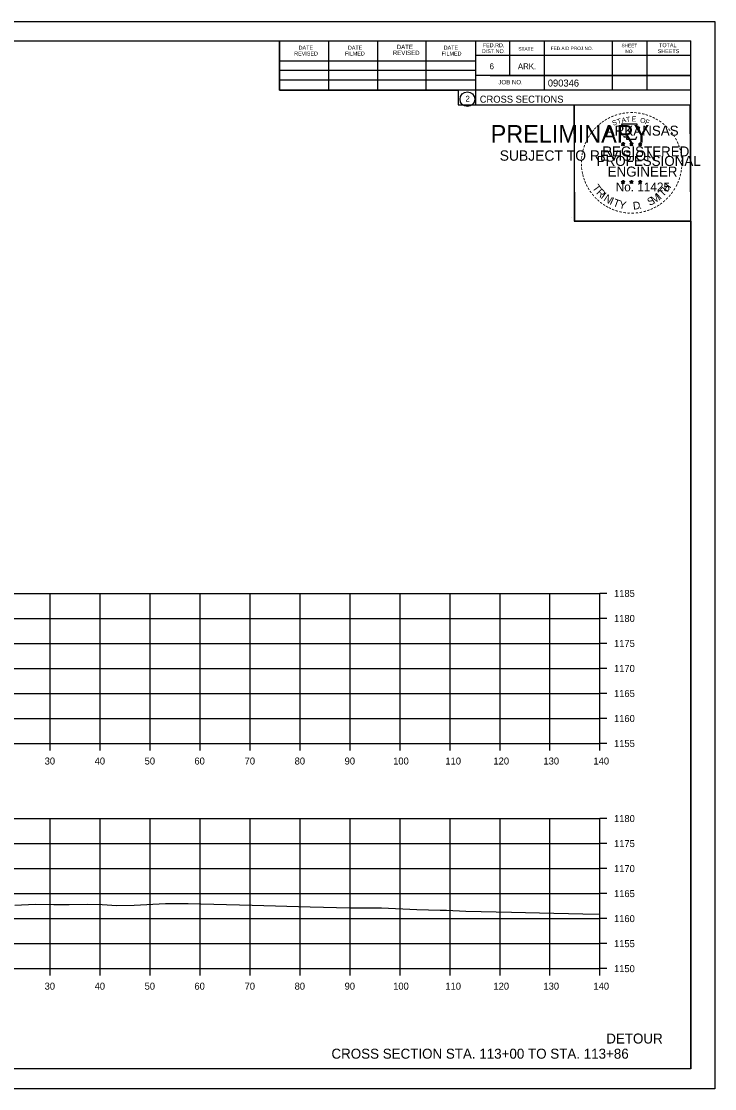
# Model space of a CAD drawing. Extents: x 1368971 to 1374497, y 378717 to 381839.
# Drawn here: x 1371286.9 to 1371425.6, y 381626.1 to 381839.4 of the extents above; entities that cross this region are included whole.
import ezdxf

# ---------------------------------------------------------------- set-up
doc = ezdxf.new("R2010")
doc.units = 0
for name, color, linetype in [('R_Axis', 7, 'Continuous'), ('R_Axis Annot', 7, 'Continuous'), ('R_Draft', 7, 'Continuous'), ('R_Exist Surface', 7, 'Continuous'), ('R_Grid', 7, 'Continuous'), ('R_No Plot', 7, 'Continuous')]:
    doc.layers.add(name, color=color, linetype=linetype)

msp = doc.modelspace()

# ---------------------------------------------------------------- linework, layer by layer
at = {"layer": 'R_Axis'}
for p, q in [((1371402.64, 381695.09), (1371402.64, 381725.09)), ((1371404.04, 381725.09), (1371402.64, 381725.09)), ((1371404.04, 381720.09), (1371402.64, 381720.09)), ((1371404.04, 381715.09), (1371402.64, 381715.09)), ((1371404.04, 381710.09), (1371402.64, 381710.09)), ((1371404.04, 381705.09), (1371402.64, 381705.09)), ((1371404.04, 381700.09), (1371402.64, 381700.09)), ((1371122.64, 381695.09), (1371402.64, 381695.09)), ((1371292.64, 381693.69), (1371292.64, 381695.09)), ((1371302.64, 381693.69), (1371302.64, 381695.09)), ((1371312.64, 381693.69), (1371312.64, 381695.09)), ((1371322.64, 381693.69), (1371322.64, 381695.09)), ((1371332.64, 381693.69), (1371332.64, 381695.09)), ((1371342.64, 381693.69), (1371342.64, 381695.09)), ((1371352.64, 381693.69), (1371352.64, 381695.09)), ((1371362.64, 381693.69), (1371362.64, 381695.09)), ((1371372.64, 381693.69), (1371372.64, 381695.09)), ((1371382.64, 381693.69), (1371382.64, 381695.09)), ((1371392.64, 381693.69), (1371392.64, 381695.09)), ((1371402.64, 381693.69), (1371402.64, 381695.09)), ((1371404.04, 381695.09), (1371402.64, 381695.09)), ((1371402.64, 381650.09), (1371402.64, 381680.09)), ((1371404.04, 381680.09), (1371402.64, 381680.09)), ((1371404.04, 381675.09), (1371402.64, 381675.09)), ((1371404.04, 381670.09), (1371402.64, 381670.09)), ((1371404.04, 381665.09), (1371402.64, 381665.09)), ((1371404.04, 381660.09), (1371402.64, 381660.09)), ((1371404.04, 381655.09), (1371402.64, 381655.09)), ((1371122.64, 381650.09), (1371402.64, 381650.09)), ((1371292.64, 381648.69), (1371292.64, 381650.09)), ((1371302.64, 381648.69), (1371302.64, 381650.09)), ((1371312.64, 381648.69), (1371312.64, 381650.09)), ((1371322.64, 381648.69), (1371322.64, 381650.09)), ((1371332.64, 381648.69), (1371332.64, 381650.09)), ((1371342.64, 381648.69), (1371342.64, 381650.09)), ((1371352.64, 381648.69), (1371352.64, 381650.09)), ((1371362.64, 381648.69), (1371362.64, 381650.09)), ((1371372.64, 381648.69), (1371372.64, 381650.09)), ((1371382.64, 381648.69), (1371382.64, 381650.09)), ((1371392.64, 381648.69), (1371392.64, 381650.09)), ((1371402.64, 381648.69), (1371402.64, 381650.09)), ((1371404.04, 381650.09), (1371402.64, 381650.09))]:
    msp.add_line(p, q, dxfattribs=at)
at = {"layer": 'R_Exist Surface'}
msp.add_lwpolyline([(1371285.58, 381662.81), (1371289.64, 381662.95), (1371293.37, 381662.89), (1371296.47, 381662.94), (1371300.23, 381662.98), (1371303.08, 381662.94), (1371306, 381662.7), (1371309.44, 381662.8), (1371315.75, 381663.08), (1371320.25, 381663.08), (1371333.1, 381662.77), (1371344.7, 381662.45), (1371352.61, 381662.24), (1371358.96, 381662.25), (1371365.99, 381661.93), (1371370.64, 381661.8), (1371371.96, 381661.81), (1371375.79, 381661.61), (1371384.93, 381661.38), (1371390.56, 381661.28), (1371399.24, 381661.07), (1371402.64, 381660.99)], dxfattribs=at)
at = {"layer": 'R_Grid'}
for p, q in [((1371122.64, 381725.09), (1371402.64, 381725.09)), ((1371292.64, 381695.09), (1371292.64, 381725.09)), ((1371302.64, 381695.09), (1371302.64, 381725.09)), ((1371312.64, 381695.09), (1371312.64, 381725.09)), ((1371322.64, 381695.09), (1371322.64, 381725.09)), ((1371332.64, 381695.09), (1371332.64, 381725.09)), ((1371342.64, 381695.09), (1371342.64, 381725.09)), ((1371352.64, 381695.09), (1371352.64, 381725.09)), ((1371362.64, 381695.09), (1371362.64, 381725.09)), ((1371372.64, 381695.09), (1371372.64, 381725.09)), ((1371382.64, 381695.09), (1371382.64, 381725.09)), ((1371392.64, 381695.09), (1371392.64, 381725.09)), ((1371402.64, 381695.09), (1371402.64, 381725.09)), ((1371122.64, 381720.09), (1371402.64, 381720.09)), ((1371122.64, 381715.09), (1371402.64, 381715.09)), ((1371122.64, 381710.09), (1371402.64, 381710.09)), ((1371122.64, 381705.09), (1371402.64, 381705.09)), ((1371122.64, 381700.09), (1371402.64, 381700.09)), ((1371122.64, 381695.09), (1371402.64, 381695.09)), ((1371122.64, 381680.09), (1371402.64, 381680.09)), ((1371292.64, 381650.09), (1371292.64, 381680.09)), ((1371302.64, 381650.09), (1371302.64, 381680.09)), ((1371312.64, 381650.09), (1371312.64, 381680.09)), ((1371322.64, 381650.09), (1371322.64, 381680.09)), ((1371332.64, 381650.09), (1371332.64, 381680.09)), ((1371342.64, 381650.09), (1371342.64, 381680.09)), ((1371352.64, 381650.09), (1371352.64, 381680.09)), ((1371362.64, 381650.09), (1371362.64, 381680.09)), ((1371372.64, 381650.09), (1371372.64, 381680.09)), ((1371382.64, 381650.09), (1371382.64, 381680.09)), ((1371392.64, 381650.09), (1371392.64, 381680.09)), ((1371402.64, 381650.09), (1371402.64, 381680.09)), ((1371122.64, 381675.09), (1371402.64, 381675.09)), ((1371122.64, 381670.09), (1371402.64, 381670.09)), ((1371122.64, 381665.09), (1371402.64, 381665.09)), ((1371122.64, 381660.09), (1371402.64, 381660.09)), ((1371122.64, 381655.09), (1371402.64, 381655.09)), ((1371122.64, 381650.09), (1371402.64, 381650.09))]:
    msp.add_line(p, q, dxfattribs=at)
at = {"layer": 'R_No Plot'}
for p, q in [((1371092.24, 381839.44), (1371425.58, 381839.44)), ((1371104.64, 381835.55), (1371420.82, 381835.55)), ((1371338.56, 381825.67), (1371338.56, 381835.55)), ((1371348.42, 381825.67), (1371348.42, 381835.35)), ((1371358.18, 381825.67), (1371358.18, 381835.35)), ((1371367.86, 381825.67), (1371367.86, 381835.35)), ((1371377.72, 381835.55), (1371377.72, 381822.75)), ((1371384.56, 381835.55), (1371384.56, 381828.61)), ((1371391.5, 381835.55), (1371391.5, 381825.67)), ((1371405.08, 381835.55), (1371405.08, 381825.67)), ((1371412.02, 381835.55), (1371412.02, 381825.67)), ((1371420.82, 381630.09), (1371420.82, 381835.55)), ((1371420.82, 381832.61), (1371377.72, 381832.61)), ((1371420.82, 381832.63), (1371420.82, 381832.63)), ((1371338.56, 381831.53), (1371377.72, 381831.53)), ((1371338.56, 381829.67), (1371377.72, 381829.67)), ((1371338.56, 381825.67), (1371338.56, 381827.73)), ((1371338.56, 381827.73), (1371377.72, 381827.73)), ((1371420.82, 381828.61), (1371377.72, 381828.61)), ((1371380.68, 381828.61), (1371420.82, 381828.61)), ((1371420.82, 381825.67), (1371338.56, 381825.67)), ((1371377.72, 381822.75), (1371420.82, 381822.75)), ((1371406.91, 381815), (1371407.26, 381814.89)), ((1371406.91, 381815), (1371407.16, 381814.96)), ((1371406.91, 381815), (1371407.15, 381814.88)), ((1371407.04, 381814.59), (1371407.26, 381814.89)), ((1371407.04, 381814.59), (1371407.17, 381814.84)), ((1371407.04, 381814.59), (1371407.26, 381814.81)), ((1371407.26, 381815.26), (1371407.22, 381815)), ((1371407.26, 381814.89), (1371407.26, 381815.26)), ((1371407.26, 381815.26), (1371407.31, 381815.01)), ((1371407.6, 381815), (1371407.26, 381814.89)), ((1371407.47, 381814.59), (1371407.26, 381814.89)), ((1371407.47, 381814.59), (1371407.26, 381814.81)), ((1371407.6, 381815), (1371407.32, 381814.95)), ((1371407.47, 381814.59), (1371407.33, 381814.89)), ((1371407.6, 381815), (1371407.4, 381814.9)), ((1371408.58, 381815), (1371408.93, 381814.89)), ((1371408.58, 381815), (1371408.83, 381814.96)), ((1371408.58, 381815), (1371408.82, 381814.88)), ((1371408.71, 381814.59), (1371408.93, 381814.89)), ((1371408.71, 381814.59), (1371408.84, 381814.84)), ((1371408.71, 381814.59), (1371408.93, 381814.81)), ((1371408.93, 381815.26), (1371408.89, 381815)), ((1371408.93, 381814.89), (1371408.93, 381815.26)), ((1371408.93, 381815.26), (1371408.98, 381815.01)), ((1371409.27, 381815), (1371408.93, 381814.89)), ((1371409.14, 381814.59), (1371408.93, 381814.89)), ((1371409.14, 381814.59), (1371408.93, 381814.81)), ((1371409.27, 381815), (1371408.99, 381814.95)), ((1371409.14, 381814.59), (1371409, 381814.89)), ((1371409.27, 381815), (1371409.07, 381814.9)), ((1371410.34, 381814.99), (1371410.69, 381814.88)), ((1371410.34, 381814.99), (1371410.6, 381814.95)), ((1371410.34, 381814.99), (1371410.58, 381814.87)), ((1371410.48, 381814.58), (1371410.69, 381814.88)), ((1371410.48, 381814.58), (1371410.6, 381814.83)), ((1371410.48, 381814.58), (1371410.69, 381814.8)), ((1371410.69, 381815.24), (1371410.65, 381814.99)), ((1371410.69, 381814.88), (1371410.69, 381815.24)), ((1371410.69, 381815.24), (1371410.74, 381814.99)), ((1371411.04, 381814.99), (1371410.69, 381814.88)), ((1371410.9, 381814.58), (1371410.69, 381814.88)), ((1371410.9, 381814.58), (1371410.69, 381814.8)), ((1371411.04, 381814.99), (1371410.75, 381814.94)), ((1371410.9, 381814.58), (1371410.77, 381814.87)), ((1371411.04, 381814.99), (1371410.83, 381814.89)), ((1371406.9, 381807.43), (1371407.25, 381807.32)), ((1371406.9, 381807.43), (1371407.16, 381807.38)), ((1371406.9, 381807.43), (1371407.14, 381807.31)), ((1371407.04, 381807.02), (1371407.25, 381807.32)), ((1371407.04, 381807.02), (1371407.16, 381807.27)), ((1371407.04, 381807.02), (1371407.25, 381807.24)), ((1371407.25, 381807.68), (1371407.21, 381807.43)), ((1371407.25, 381807.32), (1371407.25, 381807.68)), ((1371407.25, 381807.68), (1371407.3, 381807.43)), ((1371407.6, 381807.43), (1371407.25, 381807.32)), ((1371407.47, 381807.02), (1371407.25, 381807.32)), ((1371407.47, 381807.02), (1371407.25, 381807.24)), ((1371407.6, 381807.43), (1371407.31, 381807.38)), ((1371407.47, 381807.02), (1371407.33, 381807.31)), ((1371407.6, 381807.43), (1371407.4, 381807.33)), ((1371408.57, 381807.43), (1371408.92, 381807.32)), ((1371408.57, 381807.43), (1371408.83, 381807.38)), ((1371408.57, 381807.43), (1371408.81, 381807.31)), ((1371408.71, 381807.02), (1371408.92, 381807.32)), ((1371408.71, 381807.02), (1371408.83, 381807.27)), ((1371408.71, 381807.02), (1371408.92, 381807.24)), ((1371408.92, 381807.68), (1371408.88, 381807.43)), ((1371408.92, 381807.32), (1371408.92, 381807.68)), ((1371408.92, 381807.68), (1371408.97, 381807.43)), ((1371409.27, 381807.43), (1371408.92, 381807.32)), ((1371409.14, 381807.02), (1371408.92, 381807.32)), ((1371409.14, 381807.02), (1371408.92, 381807.24)), ((1371409.27, 381807.43), (1371408.98, 381807.38)), ((1371409.14, 381807.02), (1371409, 381807.31)), ((1371409.27, 381807.43), (1371409.07, 381807.33)), ((1371410.34, 381807.42), (1371410.69, 381807.31)), ((1371410.34, 381807.42), (1371410.59, 381807.37)), ((1371410.34, 381807.42), (1371410.58, 381807.3)), ((1371410.47, 381807.01), (1371410.69, 381807.31)), ((1371410.47, 381807.01), (1371410.6, 381807.26)), ((1371410.47, 381807.01), (1371410.69, 381807.23)), ((1371410.69, 381807.67), (1371410.65, 381807.42)), ((1371410.69, 381807.31), (1371410.69, 381807.67)), ((1371410.69, 381807.67), (1371410.74, 381807.42)), ((1371411.04, 381807.42), (1371410.69, 381807.31)), ((1371410.9, 381807.01), (1371410.69, 381807.31)), ((1371410.9, 381807.01), (1371410.69, 381807.23)), ((1371411.04, 381807.42), (1371410.75, 381807.37)), ((1371410.9, 381807.01), (1371410.77, 381807.3)), ((1371411.04, 381807.42), (1371410.83, 381807.32)), ((1371396.86, 381800.29), (1371396.86, 381800.29)), ((1371420.82, 381630.09), (1371104.64, 381630.09)), ((1371092.24, 381626.11), (1371425.58, 381626.11))]:
    msp.add_line(p, q, dxfattribs=at)
for points in [[(1371092.24, 381839.44), (1371425.58, 381839.44), (1371425.58, 381626.1), (1371092.24, 381626.1)], [(1371338.56, 381835.55), (1371338.56, 381825.67), (1371374.3, 381825.67), (1371374.3, 381822.75), (1371397.49, 381822.75), (1371397.49, 381799.53), (1371420.82, 381799.53), (1371420.82, 381630.09), (1371104.64, 381630.09), (1371104.64, 381835.55)], [(1371397.49, 381822.78), (1371420.59, 381822.78), (1371420.71, 381799.53), (1371397.61, 381799.53)]]:
    msp.add_lwpolyline(points, close=True, dxfattribs=at)
for points in [[(1371406.95, 381818.88), (1371407.22, 381818.05)], [(1371410.46, 381817.96), (1371410.6, 381818.24), (1371409.92, 381818.22), (1371410.07, 381818.88), (1371406.95, 381818.88)], [(1371407.26, 381815.26), (1371407.47, 381814.59), (1371406.91, 381815), (1371407.6, 381815), (1371407.04, 381814.59), (1371407.26, 381815.26)], [(1371407.44, 381816.46), (1371407.44, 381816.37), (1371408, 381816.35), (1371407.95, 381815.88), (1371409.82, 381815.88), (1371410.02, 381816.41)], [(1371408.93, 381815.26), (1371409.14, 381814.59), (1371408.58, 381815), (1371409.27, 381815), (1371408.71, 381814.59), (1371408.93, 381815.26)], [(1371410.69, 381815.24), (1371410.9, 381814.58), (1371410.34, 381814.99), (1371411.04, 381814.99), (1371410.48, 381814.58), (1371410.69, 381815.24)], [(1371407.25, 381807.68), (1371407.47, 381807.02), (1371406.9, 381807.43), (1371407.6, 381807.43), (1371407.04, 381807.02), (1371407.25, 381807.68)], [(1371408.92, 381807.68), (1371409.14, 381807.02), (1371408.57, 381807.43), (1371409.27, 381807.43), (1371408.71, 381807.02), (1371408.92, 381807.68)], [(1371410.69, 381807.67), (1371410.9, 381807.01), (1371410.34, 381807.42), (1371411.04, 381807.42), (1371410.47, 381807.01), (1371410.69, 381807.67)]]:
    msp.add_lwpolyline(points, dxfattribs=at)
for centre, radius in [((1371376.11, 381823.88), 1.47), ((1371407.26, 381814.89), 0.172), ((1371407.26, 381814.89), 0.145), ((1371407.26, 381814.89), 0.116), ((1371407.26, 381814.89), 0.0991), ((1371407.26, 381814.89), 0.0747), ((1371407.26, 381814.89), 0.0495), ((1371407.26, 381814.89), 0.0296), ((1371408.93, 381814.89), 0.172), ((1371408.93, 381814.89), 0.145), ((1371408.93, 381814.89), 0.116), ((1371408.93, 381814.89), 0.0991), ((1371408.93, 381814.89), 0.0747), ((1371408.93, 381814.89), 0.0495), ((1371408.93, 381814.89), 0.0296), ((1371410.69, 381814.88), 0.172), ((1371410.69, 381814.88), 0.145), ((1371410.69, 381814.88), 0.116), ((1371410.69, 381814.88), 0.0991), ((1371410.69, 381814.88), 0.0747), ((1371410.69, 381814.88), 0.0495), ((1371410.69, 381814.88), 0.0296), ((1371407.25, 381807.32), 0.172), ((1371407.25, 381807.32), 0.145), ((1371407.25, 381807.32), 0.116), ((1371407.25, 381807.32), 0.0991), ((1371407.25, 381807.32), 0.0747), ((1371407.25, 381807.32), 0.0495), ((1371407.25, 381807.32), 0.0296), ((1371408.92, 381807.32), 0.172), ((1371408.92, 381807.32), 0.145), ((1371408.92, 381807.32), 0.116), ((1371408.92, 381807.32), 0.0991), ((1371408.92, 381807.32), 0.0747), ((1371408.92, 381807.32), 0.0495), ((1371408.92, 381807.32), 0.0296), ((1371410.69, 381807.31), 0.172), ((1371410.69, 381807.31), 0.145), ((1371410.69, 381807.31), 0.116), ((1371410.69, 381807.31), 0.0991), ((1371410.69, 381807.31), 0.0747), ((1371410.69, 381807.31), 0.0495), ((1371410.69, 381807.31), 0.0296)]:
    msp.add_circle(centre, radius, dxfattribs=at)

# ---------------------------------------------------------------- texts
at = {"layer": 'R_Axis Annot'}
for s, p in [('1185', (1371405.44, 381724.39)), ('1180', (1371405.44, 381719.39)), ('1175', (1371405.44, 381714.39)), ('1170', (1371405.44, 381709.39)), ('1165', (1371405.44, 381704.39)), ('1160', (1371405.44, 381699.39)), ('1155', (1371405.44, 381694.39)), ('30', (1371291.56, 381690.89)), ('40', (1371301.56, 381690.89)), ('50', (1371311.56, 381690.89)), ('60', (1371321.52, 381690.89)), ('70', (1371331.56, 381690.89)), ('80', (1371341.56, 381690.89)), ('90', (1371351.56, 381690.89)), ('100', (1371361.27, 381690.89)), ('110', (1371371.72, 381690.89)), ('120', (1371381.33, 381690.89)), ('130', (1371391.33, 381690.89)), ('140', (1371401.33, 381690.89)), ('1180', (1371405.44, 381679.39)), ('1175', (1371405.44, 381674.39)), ('1170', (1371405.44, 381669.39)), ('1165', (1371405.44, 381664.39)), ('1160', (1371405.44, 381659.39)), ('1155', (1371405.44, 381654.39)), ('1150', (1371405.44, 381649.39)), ('30', (1371291.56, 381645.89)), ('40', (1371301.56, 381645.89)), ('50', (1371311.56, 381645.89)), ('60', (1371321.52, 381645.89)), ('70', (1371331.56, 381645.89)), ('80', (1371341.56, 381645.89)), ('90', (1371351.56, 381645.89)), ('100', (1371361.27, 381645.89)), ('110', (1371371.72, 381645.89)), ('120', (1371381.33, 381645.89)), ('130', (1371391.33, 381645.89)), ('140', (1371401.33, 381645.89))]:
    msp.add_text(s, height=1.4, dxfattribs=at).set_placement(p)
at = {"layer": 'R_Draft'}
for s, p in [('DETOUR', (1371403.89, 381635.12)), ('CROSS SECTION STA. 113+00 TO STA. 113+86', (1371348.93, 381632.09))]:
    msp.add_text(s, height=2, dxfattribs=at).set_placement(p)
at = {"layer": 'R_No Plot'}
for s, height, p in [('DATE', 0.782, (1371342.36, 381833.79)), ('DATE', 0.782, (1371352.22, 381833.79)), ('DATE', 0.879, (1371362, 381833.89)), ('DATE', 0.782, (1371371.38, 381833.79)), ('DIST.NO.', 0.782, (1371379, 381833.09)), ('FED.RD.', 0.782, (1371379.2, 381834.27)), ('STATE', 0.684, (1371386.32, 381833.59)), ('FED.AID PROJ.NO.', 0.684, (1371392.78, 381833.69)), ('SHEET', 0.684, (1371406.94, 381834.27)), ('NO.', 0.684, (1371407.72, 381833.09)), ('SHEETS', 0.782, (1371414.18, 381833.09)), ('TOTAL', 0.782, (1371414.46, 381834.27)), ('REVISED', 0.782, (1371341.48, 381832.61)), ('FILMED', 0.782, (1371351.64, 381832.61)), ('REVISED', 0.879, (1371361.22, 381832.71)), ('FILMED', 0.782, (1371370.98, 381832.61)), ('6', 1.17, (1371380.56, 381829.87)), ('ARK.', 1.172, (1371386.22, 381829.87)), ('JOB NO.', 0.879, (1371382.32, 381826.85)), ('2', 1.17, (1371375.73, 381823.4)), ('CROSS SECTIONS', 1.4, (1371378.59, 381823.18)), ('PRELIMINARY', 3.5, (1371380.77, 381815.21)), ('DWB', 0.01, (1371381.52, 381817.06)), ('ARKANSAS', 2, (1371403.8, 381816.59)), ('DWB', 0.01, (1371407.24, 381814.89)), ('DWB', 0.01, (1371408.91, 381814.89)), ('DWB', 0.01, (1371410.68, 381814.88)), ('SUBJECT TO REVISION', 2.0751, (1371382.58, 381811.58)), ('PROFESSIONAL', 2, (1371401.98, 381810.54)), ('REGISTERED', 2, (1371403.12, 381812.44)), ('ENGINEER', 2, (1371404.16, 381808.41)), ('No. 11425', 1.757, (1371405.79, 381805.46)), ('DWB', 0.01, (1371407.24, 381807.31)), ('DWB', 0.01, (1371408.91, 381807.31)), ('DWB', 0.01, (1371410.68, 381807.3))]:
    msp.add_text(s, height=height, dxfattribs=at).set_placement(p)
for s, height, rotation, p in [('090346', 1.4, 360, (1371392.2, 381826.41)), ('-', 1.6, 13.6301, (1371406.45, 381820.25)), ('-', 1.6, 10.2193, (1371407.13, 381820.41)), ('-', 1.6, 5.8968, (1371407.85, 381820.52)), ('-', 1.6, 0.1862, (1371408.63, 381820.59)), ('-', 1.6, 357.743, (1371409.35, 381820.58)), ('-', 1.6, 352.1617, (1371410.09, 381820.52)), ('-', 1.6, 347.2049, (1371410.81, 381820.41)), ('-', 1.6, 38.9507, (1371402.78, 381818.28)), ('-', 1.6, 36.2317, (1371403.26, 381818.66)), ('-', 1.6, 34.0636, (1371403.83, 381819.05)), ('-', 1.6, 28.7918, (1371404.43, 381819.42)), ('-', 1.6, 24.3072, (1371405.06, 381819.74)), ('S', 1, 21.594, (1371405.3, 381818.56)), ('-', 1.6, 19.1761, (1371405.7, 381820.01)), ('T', 1, 16.4036, (1371406.22, 381818.89)), ('A', 1, 11.2132, (1371407.04, 381819.14)), ('T', 1, 6.0228, (1371407.89, 381819.31)), ('E', 1, 0.8323, (1371409, 381819.42)), ('O', 1, 350.4515, (1371410.6, 381819.21)), ('F', 1, 340.0707, (1371411.56, 381818.98)), ('-', 1.6, 342.3362, (1371411.45, 381820.25)), ('-', 1.6, 337.8551, (1371412.18, 381820.03)), ('-', 1.6, 334.1211, (1371412.81, 381819.76)), ('-', 1.6, 329.6409, (1371413.39, 381819.48)), ('-', 1.6, 325.8627, (1371414.04, 381819.12)), ('-', 1.6, 320.5297, (1371414.65, 381818.69)), ('-', 1.6, 54.2325, (1371401.08, 381816.33)), ('-', 1.6, 50.6142, (1371401.5, 381816.9)), ('-', 1.6, 48.423, (1371401.9, 381817.38)), ('-', 1.6, 42.9622, (1371402.35, 381817.86)), ('-', 1.6, 315.5786, (1371415.24, 381818.2)), ('-', 1.6, 309.8797, (1371415.81, 381817.65)), ('-', 1.6, 306.6522, (1371416.34, 381817.05)), ('-', 1.4, 303.6753, (1371416.82, 381816.48)), ('-', 1.6, 72.3945, (1371399.97, 381813.95)), ('-', 1.6, 67.7743, (1371400.19, 381814.58)), ('-', 1.6, 62.8713, (1371400.44, 381815.19)), ('-', 1.6, 58.0706, (1371400.76, 381815.8)), ('-', 1.6, 299.6684, (1371417.14, 381815.88)), ('-', 1.6, 294.6628, (1371417.47, 381815.26)), ('-', 1.6, 290.5728, (1371417.72, 381814.69)), ('-', 1.6, 85.1863, (1371399.56, 381811.83)), ('-', 1.6, 81.2013, (1371399.64, 381812.52)), ('-', 1.6, 75.461, (1371399.77, 381813.23)), ('-', 1.6, 285.1233, (1371417.96, 381814.11)), ('-', 1.6, 280.5493, (1371418.16, 381813.36)), ('-', 1.6, 276.5962, (1371418.32, 381812.6)), ('-', 1.6, 94.1959, (1371399.57, 381810.4)), ('-', 1.6, 89.0622, (1371399.54, 381811.13)), ('-', 1.6, 263.5172, (1371418.4, 381810.58)), ('-', 1.6, 274.3301, (1371418.38, 381811.87)), ('-', 1.6, 269.9407, (1371418.41, 381811.24)), ('-', 1.6, 98.9479, (1371399.64, 381809.74)), ('-', 1.6, 101.7149, (1371399.78, 381809)), ('-', 1.6, 105.4578, (1371399.94, 381808.41)), ('-', 1.6, 109.0874, (1371400.16, 381807.78)), ('-', 1.6, 252.8681, (1371418.03, 381808.52)), ('-', 1.6, 255.7626, (1371418.21, 381809.24)), ('-', 1.6, 260.9953, (1371418.32, 381809.92)), ('-', 1.6, 114.0643, (1371400.41, 381807.18)), ('-', 1.6, 115.7288, (1371400.71, 381806.56)), ('-', 1.6, 120.4471, (1371401.07, 381805.98)), ('T', 1.54, 306.0406, (1371401.01, 381806.16)), ('R', 1.54, 314.005, (1371401.78, 381805.11)), ('T', 1.54, 46.6444, (1371415.24, 381804.25)), ('H', 1.54, 54.6088, (1371416.13, 381805.19)), ('-', 1.6, 239.0712, (1371417.15, 381806.47)), ('-', 1.6, 244.6197, (1371417.55, 381807.22)), ('-', 1.6, 247.8887, (1371417.81, 381807.85)), ('-', 1.6, 125.8934, (1371401.47, 381805.42)), ('-', 1.6, 130.7181, (1371401.94, 381804.87)), ('-', 1.6, 134.2238, (1371402.45, 381804.32)), ('I', 1.54, 321.9694, (1371402.68, 381804.18)), ('N', 1.54, 326.5002, (1371403.24, 381803.7)), ('I', 1.54, 335.3603, (1371404.45, 381802.92)), ('T', 1.54, 339.8912, (1371405.11, 381802.59)), ('S', 1.54, 26.9312, (1371412.56, 381802.52)), ('M', 1.54, 32.6563, (1371413.4, 381802.92)), ('I', 1.54, 42.1136, (1371414.68, 381803.77)), ('-', 1.6, 225.7653, (1371415.84, 381804.69)), ('-', 1.6, 231.2538, (1371416.32, 381805.25)), ('-', 1.6, 233.8452, (1371416.75, 381805.82)), ('-', 1.6, 138.9338, (1371402.98, 381803.86)), ('-', 1.6, 144.6463, (1371403.53, 381803.45)), ('-', 1.6, 148.0898, (1371404.1, 381803.08)), ('-', 1.6, 151.5704, (1371404.67, 381802.75)), ('-', 1.6, 154.6002, (1371405.2, 381802.51)), ('-', 1.6, 158.5612, (1371405.82, 381802.25)), ('Y', 1.54, 347.8556, (1371406.33, 381802.15)), ('D', 1.54, 6.3969, (1371409.31, 381801.79)), ('.', 1.54, 13.7642, (1371410.51, 381801.91)), ('-', 1.6, 200.7184, (1371412.44, 381802.38)), ('-', 1.6, 204.2516, (1371413.06, 381802.65)), ('-', 1.6, 207.3568, (1371413.68, 381802.97)), ('-', 1.6, 212.2491, (1371414.24, 381803.32)), ('-', 1.6, 215.7363, (1371414.77, 381803.71)), ('-', 1.6, 221.0851, (1371415.32, 381804.18)), ('-', 1.6, 162.7983, (1371406.51, 381802.04)), ('-', 1.6, 167.5555, (1371407.22, 381801.88)), ('-', 1.6, 173.1155, (1371407.99, 381801.77)), ('-', 1.6, 176.5183, (1371408.74, 381801.71)), ('-', 1.6, 181.5918, (1371409.49, 381801.73)), ('-', 1.6, 185.8167, (1371410.3, 381801.81)), ('-', 1.6, 191.2858, (1371411.03, 381801.94)), ('-', 1.6, 195.4743, (1371411.76, 381802.14))]:
    msp.add_text(s, height=height, rotation=rotation, dxfattribs=at).set_placement(p)

doc.saveas('drawing.dxf')
